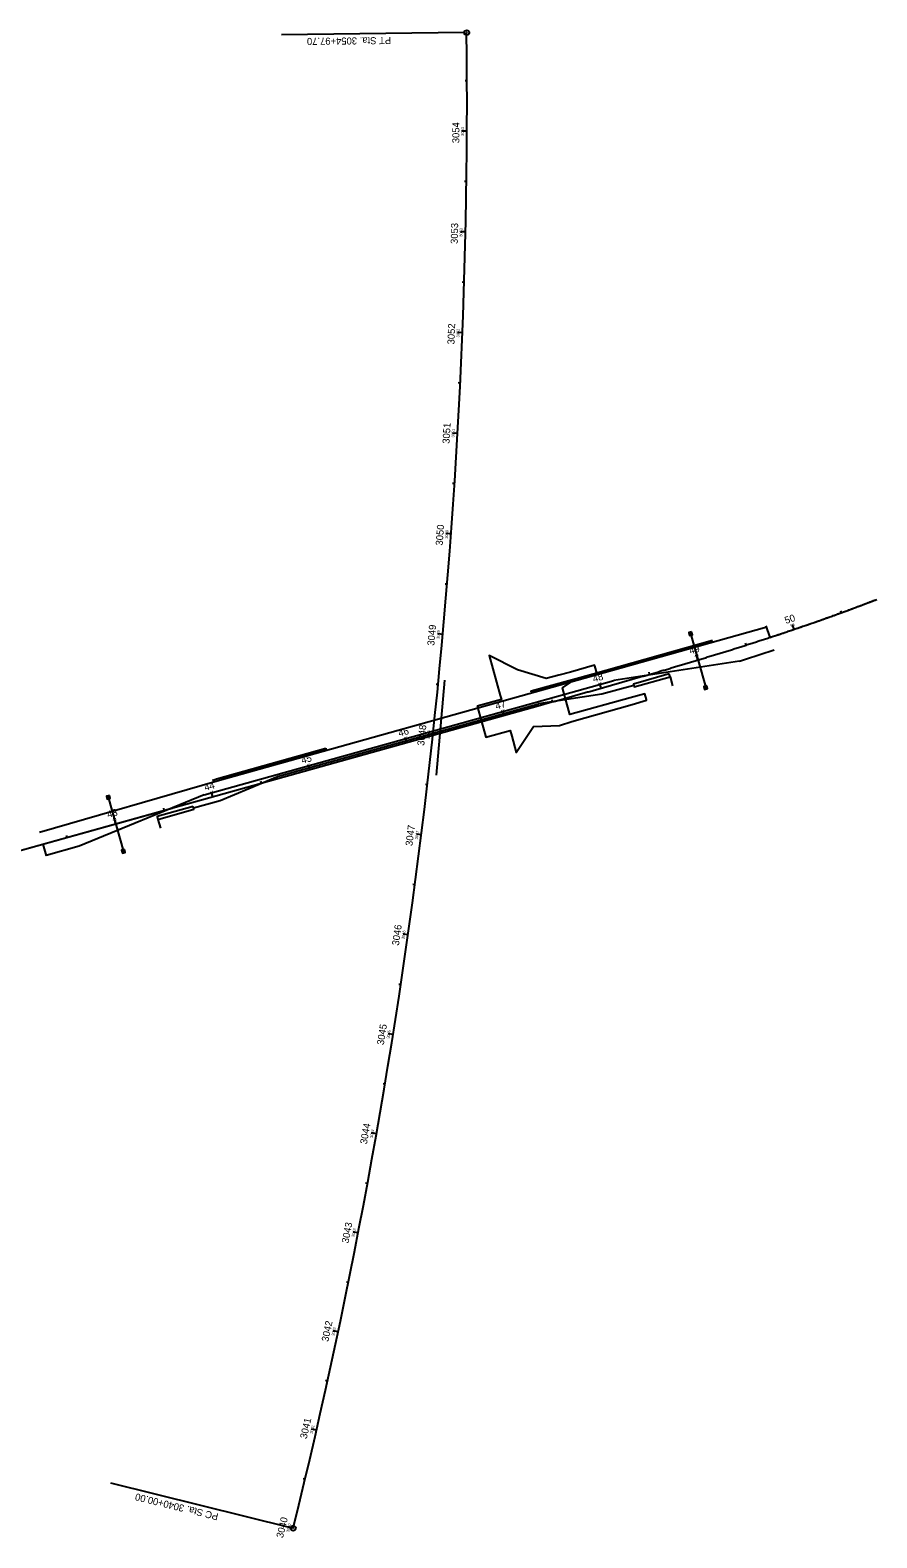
# Model space of a CAD drawing. Extents: x 1512289 to 1610162, y 552531 to 645498.
# Drawn here: x 1542833 to 1543673, y 586592 to 588088 of the extents above; entities that cross this region are included whole.
import ezdxf

# ---------------------------------------------------------------- set-up
doc = ezdxf.new("R2010")
doc.units = 0
for name, color, linetype in [('DT_P_TIN_Hull', 7, 'Continuous'), ('GE_X_CL_20', 7, 'Continuous'), ('GE_X_CL_50', 7, 'Continuous'), ('GK_Visualization', 7, 'Continuous'), ('MT_P_CL_Double_Solid', 7, 'Continuous'), ('MT_P_Drums', 7, 'Continuous'), ('MT_P_Edge_Line', 7, 'Continuous'), ('MT_P_PCB', 7, 'Continuous'), ('MT_P_Signal', 7, 'Continuous'), ('MT_P_Stop_Line', 7, 'Continuous'), ('MT_P_Temp_Road', 7, 'Continuous'), ('MT_P_Traffic_Attenuator', 7, 'Continuous'), ('PM_P_Removal', 7, 'Continuous'), ('SC_Shading2', 7, 'Continuous'), ('SG_P_Poles', 7, 'Continuous')]:
    doc.layers.add(name, color=color, linetype=linetype)

msp = doc.modelspace()

# ---------------------------------------------------------------- linework, layer by layer
at = {"layer": 'DT_P_TIN_Hull'}
msp.add_line((1543236.2, 587349), (1543244.4, 587443.4), dxfattribs=at)
msp.add_lwpolyline([(1543276.5, 587417.6), (1543280.8, 587402.2), (1543285.1, 587386.8), (1543309.2, 587393.5), (1543310.8, 587387.7), (1543315.3, 587371.7), (1543332.3, 587397.5), (1543358.1, 587398.2), (1543370.5, 587402.2), (1543430.2, 587419.3), (1543444.6, 587423.4), (1543444.4, 587424.3), (1543442.8, 587429.9), (1543428.3, 587425.8), (1543368.5, 587409.4), (1543367.5, 587412.9), (1543361.1, 587435.7), (1543371.6, 587442.6), (1543395.7, 587449.2), (1543393.3, 587457.6), (1543393.1, 587458.3), (1543369.2, 587451.3), (1543357.5, 587448.4), (1543345, 587445.1), (1543316.7, 587453.5), (1543288.5, 587467.7), (1543299.5, 587428.2), (1543300.6, 587424.3)], close=True, dxfattribs=at)
at = {"layer": 'GE_X_CL_20'}
for p, q in [((1543266.5, 588038), (1543264.5, 588038)), ((1543266.5, 587988), (1543264.5, 587988)), ((1543266, 587938), (1543264, 587938)), ((1543265, 587888), (1543263, 587888)), ((1543263.7, 587838), (1543261.7, 587838.1)), ((1543262, 587788), (1543260, 587788.1)), ((1543259.8, 587738.1), (1543257.8, 587738.2)), ((1543257.2, 587688.2), (1543255.2, 587688.3)), ((1543254.2, 587638.3), (1543252.2, 587638.4)), ((1543250.7, 587588.4), (1543248.7, 587588.5)), ((1543246.9, 587538.5), (1543244.9, 587538.7)), ((1543638, 587510.3), (1543637.3, 587512.2)), ((1543242.6, 587488.7), (1543240.6, 587488.9)), ((1543590.9, 587493.7), (1543590.2, 587495.6)), ((1543543.4, 587478.2), (1543542.7, 587480.1)), ((1543495.6, 587463.4), (1543495, 587465.3)), ((1543447.6, 587449.2), (1543447.1, 587451.1)), ((1543237.9, 587438.9), (1543235.9, 587439.1)), ((1543399.6, 587435.4), (1543399, 587437.3)), ((1541212.2, 586824.2), (1543339.3, 587418.5)), ((1543351.4, 587421.9), (1543350.9, 587423.8)), ((1543255.1, 587395), (1543254.6, 587396.9)), ((1543303.3, 587408.4), (1543302.7, 587410.4)), ((1543207, 587381.5), (1543206.4, 587383.5)), ((1543232.7, 587389.2), (1543230.8, 587389.4)), ((1543158.8, 587368.1), (1543158.3, 587370)), ((1543110.7, 587354.6), (1543110.1, 587356.6)), ((1543062.5, 587341.2), (1543062, 587343.1)), ((1543227.2, 587339.5), (1543225.2, 587339.7)), ((1543014.4, 587327.7), (1543013.8, 587329.6)), ((1542966.2, 587314.3), (1542965.7, 587316.2)), ((1542918, 587300.8), (1542917.5, 587302.7)), ((1542869.9, 587287.3), (1542869.3, 587289.3)), ((1543221.2, 587289.9), (1543219.3, 587290.1)), ((1543214.9, 587240.3), (1543212.9, 587240.5)), ((1543208.1, 587190.7), (1543206.1, 587191)), ((1543200.9, 587141.3), (1543198.9, 587141.5)), ((1543193.2, 587091.8), (1543191.2, 587092.2)), ((1543185.2, 587042.5), (1543183.2, 587042.8)), ((1543176.7, 586993.2), (1543174.7, 586993.6)), ((1543167.8, 586944), (1543165.9, 586944.4)), ((1543158.5, 586894.9), (1543156.6, 586895.3)), ((1543148.8, 586845.8), (1543146.9, 586846.2)), ((1543138.7, 586796.9), (1543136.7, 586797.3)), ((1543128.2, 586748), (1543126.2, 586748.4)), ((1543117.2, 586699.2), (1543115.3, 586699.6)), ((1543105.9, 586650.5), (1543103.9, 586651)), ((1543094.1, 586601.9), (1543092.2, 586602.4))]:
    msp.add_line(p, q, dxfattribs=at)
msp.add_arc((1537339.3, 588021.3), 5927.2, 346.14519, 0.6228, dxfattribs=at)
msp.add_spline([(1543339.3, 587418.5), (1543343.8, 587419.8), (1543348.4, 587421.1), (1543353, 587422.3), (1543357.5, 587423.6), (1543362.1, 587424.9), (1543366.6, 587426.1), (1543371.2, 587427.4), (1543375.7, 587428.7), (1543380.3, 587430), (1543384.8, 587431.3), (1543389.4, 587432.5), (1543393.9, 587433.8), (1543398.5, 587435.1), (1543403, 587436.4), (1543407.6, 587437.7), (1543412.1, 587439), (1543416.7, 587440.3), (1543421.2, 587441.6), (1543425.8, 587442.9), (1543430.3, 587444.2), (1543434.9, 587445.5), (1543439.4, 587446.8), (1543444, 587448.1), (1543448.5, 587449.4), (1543453, 587450.7), (1543457.6, 587452.1), (1543462.1, 587453.4), (1543466.7, 587454.7), (1543471.2, 587456.1), (1543475.7, 587457.4), (1543480.3, 587458.8), (1543484.8, 587460.1), (1543489.3, 587461.5), (1543493.9, 587462.8), (1543498.4, 587464.2), (1543502.9, 587465.6), (1543507.4, 587467), (1543512, 587468.3), (1543516.5, 587469.7), (1543521, 587471.1), (1543525.5, 587472.5), (1543530, 587473.9), (1543534.5, 587475.4), (1543539.1, 587476.8), (1543543.6, 587478.2), (1543548.1, 587479.7), (1543552.6, 587481.1), (1543557.1, 587482.6), (1543561.6, 587484), (1543566.1, 587485.5), (1543570.6, 587487), (1543575.1, 587488.4), (1543579.5, 587489.9), (1543584, 587491.4), (1543588.5, 587493), (1543593, 587494.5), (1543597.5, 587496), (1543601.9, 587497.5), (1543606.4, 587499.1), (1543610.9, 587500.6), (1543615.3, 587502.2), (1543619.8, 587503.8), (1543624.3, 587505.4), (1543628.7, 587506.9), (1543633.2, 587508.6), (1543637.6, 587510.2), (1543642, 587511.8), (1543646.5, 587513.4), (1543650.9, 587515.1), (1543655.3, 587516.7), (1543659.8, 587518.4), (1543664.2, 587520.1), (1543668.6, 587521.8), (1543673, 587523.5)], degree=3, dxfattribs=at)
at = {"layer": 'GE_X_CL_50'}
for p, q in [((1543263.7, 588085.7), (1543082.4, 588083.7)), ((1543266.5, 587988), (1543261.5, 587988)), ((1543265, 587888), (1543260, 587888.1)), ((1543262, 587788), (1543257, 587788.2)), ((1543257.2, 587688.2), (1543252.2, 587688.4)), ((1543250.7, 587588.4), (1543245.7, 587588.7)), ((1543242.6, 587488.7), (1543237.6, 587489.2)), ((1543590.9, 587493.7), (1543589.3, 587498.5)), ((1543495.6, 587463.4), (1543494.1, 587468.1)), ((1543399.6, 587435.4), (1543398.2, 587440.2)), ((1541212.2, 586824.2), (1543339.3, 587418.5)), ((1543303.3, 587408.4), (1543301.9, 587413.3)), ((1543207, 587381.5), (1543205.6, 587386.4)), ((1543232.7, 587389.2), (1543227.8, 587389.7)), ((1543110.7, 587354.6), (1543109.3, 587359.4)), ((1543014.4, 587327.7), (1543013, 587332.5)), ((1542918, 587300.8), (1542916.7, 587305.6)), ((1543221.2, 587289.9), (1543216.3, 587290.5)), ((1543208.1, 587190.7), (1543203.1, 587191.4)), ((1543193.2, 587091.8), (1543188.3, 587092.6)), ((1543176.7, 586993.2), (1543171.8, 586994.1)), ((1543158.5, 586894.9), (1543153.6, 586895.8)), ((1543138.7, 586796.9), (1543133.8, 586797.9)), ((1543117.2, 586699.2), (1543112.3, 586700.3)), ((1543091.7, 586602.5), (1542913.1, 586646.6)), ((1543094.1, 586601.9), (1543089.2, 586603.1))]:
    msp.add_line(p, q, dxfattribs=at)
for centre in [(1543266.2, 588085.7), (1543094.1, 586601.9)]:
    msp.add_circle(centre, 2.5, dxfattribs=at)
msp.add_arc((1537339.3, 588021.3), 5927.2, 346.14519, 0.6228, dxfattribs=at)
msp.add_spline([(1543339.3, 587418.5), (1543343.8, 587419.8), (1543348.4, 587421.1), (1543353, 587422.3), (1543357.5, 587423.6), (1543362.1, 587424.9), (1543366.6, 587426.1), (1543371.2, 587427.4), (1543375.7, 587428.7), (1543380.3, 587430), (1543384.8, 587431.3), (1543389.4, 587432.5), (1543393.9, 587433.8), (1543398.5, 587435.1), (1543403, 587436.4), (1543407.6, 587437.7), (1543412.1, 587439), (1543416.7, 587440.3), (1543421.2, 587441.6), (1543425.8, 587442.9), (1543430.3, 587444.2), (1543434.9, 587445.5), (1543439.4, 587446.8), (1543444, 587448.1), (1543448.5, 587449.4), (1543453, 587450.7), (1543457.6, 587452.1), (1543462.1, 587453.4), (1543466.7, 587454.7), (1543471.2, 587456.1), (1543475.7, 587457.4), (1543480.3, 587458.8), (1543484.8, 587460.1), (1543489.3, 587461.5), (1543493.9, 587462.8), (1543498.4, 587464.2), (1543502.9, 587465.6), (1543507.4, 587467), (1543512, 587468.3), (1543516.5, 587469.7), (1543521, 587471.1), (1543525.5, 587472.5), (1543530, 587473.9), (1543534.5, 587475.4), (1543539.1, 587476.8), (1543543.6, 587478.2), (1543548.1, 587479.7), (1543552.6, 587481.1), (1543557.1, 587482.6), (1543561.6, 587484), (1543566.1, 587485.5), (1543570.6, 587487), (1543575.1, 587488.4), (1543579.5, 587489.9), (1543584, 587491.4), (1543588.5, 587493), (1543593, 587494.5), (1543597.5, 587496), (1543601.9, 587497.5), (1543606.4, 587499.1), (1543610.9, 587500.6), (1543615.3, 587502.2), (1543619.8, 587503.8), (1543624.3, 587505.4), (1543628.7, 587506.9), (1543633.2, 587508.6), (1543637.6, 587510.2), (1543642, 587511.8), (1543646.5, 587513.4), (1543650.9, 587515.1), (1543655.3, 587516.7), (1543659.8, 587518.4), (1543664.2, 587520.1), (1543668.6, 587521.8), (1543673, 587523.5)], degree=3, dxfattribs=at)
at = {"layer": 'GK_Visualization'}
for p, q in [((1543266.3, 588085.7), (1543266.1, 588085.7)), ((1543266.2, 588085.8), (1543266.2, 588085.6)), ((1543673.1, 587523.5), (1543673, 587523.5)), ((1543673, 587523.5), (1543673, 587523.4)), ((1543673.1, 587523.5), (1543673, 587523.5)), ((1543564.1, 587481.4), (1543564.1, 587481.3)), ((1543564.2, 587481.3), (1543564.1, 587481.3)), ((1541212.2, 586824.2), (1543339.3, 587418.5)), ((1543339.4, 587418.5), (1543339.2, 587418.5)), ((1543339.3, 587418.6), (1543339.3, 587418.4)), ((1543094.2, 586601.9), (1543094, 586601.9)), ((1543094.1, 586602), (1543094.1, 586601.8))]:
    msp.add_line(p, q, dxfattribs=at)
msp.add_arc((1537339.3, 588021.3), 5927.2, 346.14519, 0.6228, dxfattribs=at)
msp.add_arc((1537339.3, 588021.3), 5927.2, 346.14519, 0.6228, dxfattribs=at)
msp.add_spline([(1543339.3, 587418.5), (1543343.8, 587419.8), (1543348.4, 587421.1), (1543353, 587422.3), (1543357.5, 587423.6), (1543362.1, 587424.9), (1543366.6, 587426.1), (1543371.2, 587427.4), (1543375.7, 587428.7), (1543380.3, 587430), (1543384.8, 587431.3), (1543389.4, 587432.5), (1543393.9, 587433.8), (1543398.5, 587435.1), (1543403, 587436.4), (1543407.6, 587437.7), (1543412.1, 587439), (1543416.7, 587440.3), (1543421.2, 587441.6), (1543425.8, 587442.9), (1543430.3, 587444.2), (1543434.9, 587445.5), (1543439.4, 587446.8), (1543444, 587448.1), (1543448.5, 587449.4), (1543453, 587450.7), (1543457.6, 587452.1), (1543462.1, 587453.4), (1543466.7, 587454.7), (1543471.2, 587456.1), (1543475.7, 587457.4), (1543480.3, 587458.8), (1543484.8, 587460.1), (1543489.3, 587461.5), (1543493.9, 587462.8), (1543498.4, 587464.2), (1543502.9, 587465.6), (1543507.4, 587467), (1543512, 587468.3), (1543516.5, 587469.7), (1543521, 587471.1), (1543525.5, 587472.5), (1543530, 587473.9), (1543534.5, 587475.4), (1543539.1, 587476.8), (1543543.6, 587478.2), (1543548.1, 587479.7), (1543552.6, 587481.1), (1543557.1, 587482.6), (1543561.6, 587484), (1543566.1, 587485.5), (1543570.6, 587487), (1543575.1, 587488.4), (1543579.5, 587489.9), (1543584, 587491.4), (1543588.5, 587493), (1543593, 587494.5), (1543597.5, 587496), (1543601.9, 587497.5), (1543606.4, 587499.1), (1543610.9, 587500.6), (1543615.3, 587502.2), (1543619.8, 587503.8), (1543624.3, 587505.4), (1543628.7, 587506.9), (1543633.2, 587508.6), (1543637.6, 587510.2), (1543642, 587511.8), (1543646.5, 587513.4), (1543650.9, 587515.1), (1543655.3, 587516.7), (1543659.8, 587518.4), (1543664.2, 587520.1), (1543668.6, 587521.8), (1543673, 587523.5)], degree=3, dxfattribs=at)
msp.add_spline([(1543339.3, 587418.5), (1543343.8, 587419.8), (1543348.4, 587421.1), (1543353, 587422.3), (1543357.5, 587423.6), (1543362.1, 587424.9), (1543366.6, 587426.1), (1543371.2, 587427.4), (1543375.7, 587428.7), (1543380.3, 587430), (1543384.8, 587431.3), (1543389.4, 587432.5), (1543393.9, 587433.8), (1543398.5, 587435.1), (1543403, 587436.4), (1543407.6, 587437.7), (1543412.1, 587439), (1543416.7, 587440.3), (1543421.2, 587441.6), (1543425.8, 587442.9), (1543430.3, 587444.2), (1543434.9, 587445.5), (1543439.4, 587446.8), (1543444, 587448.1), (1543448.5, 587449.4), (1543453, 587450.7), (1543457.6, 587452.1), (1543462.1, 587453.4), (1543466.7, 587454.7), (1543471.2, 587456.1), (1543475.7, 587457.4), (1543480.3, 587458.8), (1543484.8, 587460.1), (1543489.3, 587461.5), (1543493.9, 587462.8), (1543498.4, 587464.2), (1543502.9, 587465.6), (1543507.4, 587467), (1543512, 587468.3), (1543516.5, 587469.7), (1543521, 587471.1), (1543525.5, 587472.5), (1543530, 587473.9), (1543534.5, 587475.4), (1543539.1, 587476.8), (1543543.6, 587478.2), (1543548.1, 587479.7), (1543552.6, 587481.1), (1543557.1, 587482.6), (1543561.6, 587484), (1543566.1, 587485.5), (1543570.6, 587487), (1543575.1, 587488.4), (1543579.5, 587489.9), (1543584, 587491.4), (1543588.5, 587493), (1543593, 587494.5), (1543597.5, 587496), (1543601.9, 587497.5), (1543606.4, 587499.1), (1543610.9, 587500.6), (1543615.3, 587502.2), (1543619.8, 587503.8), (1543624.3, 587505.4), (1543628.7, 587506.9), (1543633.2, 587508.6), (1543637.6, 587510.2), (1543642, 587511.8), (1543646.5, 587513.4), (1543650.9, 587515.1), (1543655.3, 587516.7), (1543659.8, 587518.4), (1543664.2, 587520.1), (1543668.6, 587521.8), (1543673, 587523.5)], degree=3, dxfattribs=at)
at = {"layer": 'MT_P_CL_Double_Solid'}
msp.add_line((1542364.3, 587146), (1542845.8, 587280.6), dxfattribs=at)
msp.add_open_spline([(1543567.1, 587485.8), (1543576.4, 587488.9), (1543581.4, 587490.5), (1543597.7, 587496.1), (1543604.5, 587498.4), (1543618.3, 587503.2), (1543625.2, 587505.7), (1543638.9, 587510.6), (1543645.7, 587513.1), (1543654.3, 587516.3), (1543656.8, 587517.3), (1543659.8, 587518.4), (1543661.3, 587519), (1543662.1, 587519.3), (1543662.4, 587519.4), (1543662.6, 587519.5), (1543662.7, 587519.5), (1543663, 587519.6), (1543663.3, 587519.8), (1543663.7, 587519.9), (1543663.9, 587520), (1543664, 587520), (1543664.3, 587520.1), (1543664.5, 587520.2), (1543664.9, 587520.4), (1543665.2, 587520.4), (1543665.8, 587520.7), (1543666.2, 587520.8), (1543667.1, 587521.2), (1543667.5, 587521.3), (1543668, 587521.5), (1543668.1, 587521.6), (1543668.3, 587521.7), (1543668.5, 587521.7), (1543668.7, 587521.8), (1543668.8, 587521.8), (1543669, 587521.9), (1543669.1, 587521.9), (1543669.6, 587522.2), (1543670, 587522.3), (1543671.3, 587522.8), (1543672.2, 587523.1), (1543673, 587523.5)], degree=3, dxfattribs=at)
at = {"layer": 'MT_P_Drums'}
for p, q in [((1543468, 587446.6), (1543470.4, 587437.8)), ((1542959.9, 587305.2), (1542962.3, 587296.4))]:
    msp.add_line(p, q, dxfattribs=at)
at = {"layer": 'MT_P_Edge_Line'}
for p, q in [((1543392, 587447.8), (1543563.8, 587496.1)), ((1543536.7, 587462.2), (1543412, 587443)), ((1543005.9, 587329.5), (1543412, 587443)), ((1543018.6, 587343.4), (1543392, 587447.8)), ((1542842.5, 587292.5), (1543018.6, 587343.4)), ((1543005.9, 587329.5), (1542881.7, 587278.6)), ((1542881.7, 587278.6), (1542848.9, 587269.4))]:
    msp.add_line(p, q, dxfattribs=at)
msp.add_lwpolyline([(1543536.7, 587462.2), (1543542.9, 587464.2), (1543571.2, 587473.4)], dxfattribs=at)
at = {"layer": 'MT_P_PCB'}
for p, q in [((1543400.3, 587429.4), (1543337.3, 587420)), ((1543431.9, 587438), (1543400.3, 587429.4)), ((1543078.5, 587347.7), (1543337.3, 587420)), ((1543021.8, 587323.9), (1543078.5, 587347.7)), ((1542995.1, 587316.7), (1543021.8, 587323.9))]:
    msp.add_line(p, q, dxfattribs=at)
at = {"layer": 'MT_P_Signal'}
for p, q in [((1543488.3, 587489.5), (1543503.3, 587435.9)), ((1542910.6, 587327.1), (1542925.6, 587273.5))]:
    msp.add_line(p, q, dxfattribs=at)
at = {"layer": 'MT_P_Stop_Line'}
for p, q in [((1543567.1, 587485.8), (1543563.4, 587497.3)), ((1542845.8, 587280.6), (1542849, 587269))]:
    msp.add_line(p, q, dxfattribs=at)
at = {"layer": 'MT_P_Temp_Road'}
for p, q in [((1543391.5, 587449.7), (1543509.9, 587483)), ((1543330.1, 587432.6), (1543391.5, 587449.7)), ((1543017.9, 587345.3), (1543126.5, 587375.7)), ((1543013.9, 587343.7), (1543017.9, 587345.3))]:
    msp.add_line(p, q, dxfattribs=at)
at = {"layer": 'MT_P_Traffic_Attenuator'}
for points in [[(1543467.1, 587449.5), (1543431.5, 587439.5), (1543432.3, 587436.6), (1543468, 587446.6)], [(1542994.7, 587318.1), (1542959, 587308.1), (1542959.9, 587305.2), (1542995.5, 587315.3)]]:
    msp.add_lwpolyline(points, close=True, dxfattribs=at)
at = {"layer": 'PM_P_Removal'}
msp.add_line((1542845.8, 587280.6), (1542974.1, 587316.5), dxfattribs=at)
at = {"layer": 'SC_Shading2'}
for p, q in [((1543391.5, 587449.7), (1543509.9, 587483)), ((1543330.1, 587432.6), (1543391.5, 587449.7)), ((1543330, 587431.8), (1543330.1, 587432.6)), ((1543017.9, 587345.3), (1543126.5, 587375.7)), ((1543126.5, 587375.7), (1543126.5, 587375)), ((1543013.9, 587343.7), (1543017.9, 587345.3))]:
    msp.add_line(p, q, dxfattribs=at)
for centre, radius, start, end in [((1542551, 590509.9), 3175.2, 284.2029, 287.5783), ((1826487.6, -430451.8), 1056534.4, 105.5571063, 105.5634425)]:
    msp.add_arc(centre, radius, start, end, dxfattribs=at)
at = {"layer": 'SG_P_Poles'}
for points in [[(1543489.3, 587491.3), (1543486.4, 587490.5), (1543487.3, 587487.6), (1543490.1, 587488.4)], [(1543504.3, 587437.8), (1543501.4, 587437), (1543502.2, 587434.1), (1543505.1, 587434.9)], [(1542911.7, 587328.9), (1542908.8, 587328.1), (1542909.6, 587325.2), (1542912.5, 587326.1)], [(1542926.7, 587275.4), (1542923.8, 587274.6), (1542924.6, 587271.7), (1542927.5, 587272.5)]]:
    msp.add_lwpolyline(points, close=True, dxfattribs=at)
for centre in [(1543488.3, 587489.5), (1543503.3, 587435.9), (1542910.6, 587327.1), (1542925.6, 587273.5)]:
    msp.add_circle(centre, 1.2, dxfattribs=at)

# ---------------------------------------------------------------- texts
at = {"layer": 'GE_X_CL_20'}
for s, rotation, p in [('3054', 89.6784, (1543263.4, 587983.2)), ('3053', 88.7117, (1543261.9, 587883.2)), ('3052', 87.7451, (1543258.8, 587783.3)), ('3051', 86.7784, (1543253.9, 587684)), ('3050', 85.8117, (1543247.4, 587583.7)), ('3049', 84.8451, (1543239.1, 587484.1)), ('50', 18.7311, (1543587.7, 587495.8)), ('49', 16.8074, (1543492.5, 587465.6)), ('48', 15.7885, (1543396.6, 587437.7)), ('47', 15.6111, (1543300.2, 587410.7)), ('46', 15.6111, (1543203.9, 587383.8)), ('3048', 83.8784, (1543229.3, 587384.7)), ('45', 15.6111, (1543107.6, 587356.9)), ('44', 15.6111, (1543011.4, 587330)), ('43', 15.6111, (1542915, 587303.1)), ('3047', 82.9118, (1543217.7, 587285.3)), ('3046', 81.9451, (1543204.4, 587186.3)), ('3045', 80.9785, (1543189.5, 587087.5)), ('3044', 80.0118, (1543172.9, 586989)), ('3043', 79.0452, (1543154.7, 586890.7)), ('3042', 78.0785, (1543134.8, 586792.7)), ('3041', 77.1118, (1543113.3, 586695.6)), ('3040', 76.1452, (1543090, 586597.9))]:
    msp.add_text(s, height=2.8, rotation=rotation, dxfattribs=at).set_placement(p)
at = {"layer": 'GE_X_CL_50'}
for s, rotation, p in [('PT Sta. 3054+97.70', 180.6228, (1543191.2, 588081.4)), ('3054', 89.6784, (1543258.9, 587976)), ('3053', 88.7117, (1543257.3, 587876)), ('3052', 87.7451, (1543254, 587776.3)), ('3051', 86.7784, (1543249.1, 587677.7)), ('3050', 85.8117, (1543242.3, 587576.7)), ('50', 18.7311, (1543582.9, 587499)), ('3049', 84.8451, (1543234, 587477.3)), ('49', 16.8074, (1543488, 587468.9)), ('48', 15.7885, (1543392.2, 587441.1)), ('47', 15.6111, (1543295.6, 587414.1)), ('3048', 83.8784, (1543224, 587378)), ('46', 15.6111, (1543199.4, 587387.2)), ('45', 15.6111, (1543103.1, 587360.3)), ('44', 15.6111, (1543006.9, 587333.4)), ('43', 15.6111, (1542910.5, 587306.5)), ('3047', 82.9118, (1543212.3, 587278.5)), ('3046', 81.9451, (1543198.9, 587179.7)), ('3045', 80.9785, (1543183.9, 587081)), ('3044', 80.0118, (1543167.2, 586982.6)), ('3043', 79.0452, (1543148.9, 586884.3)), ('3042', 78.0785, (1543128.9, 586786.6)), ('3041', 77.1118, (1543107.5, 586690.2)), ('PC Sta. 3040+00.00', 166.1452, (1543020.4, 586616.5)), ('3040', 76.1452, (1543083.9, 586591.8))]:
    msp.add_text(s, height=7, rotation=rotation, dxfattribs=at).set_placement(p)

doc.saveas('drawing.dxf')
